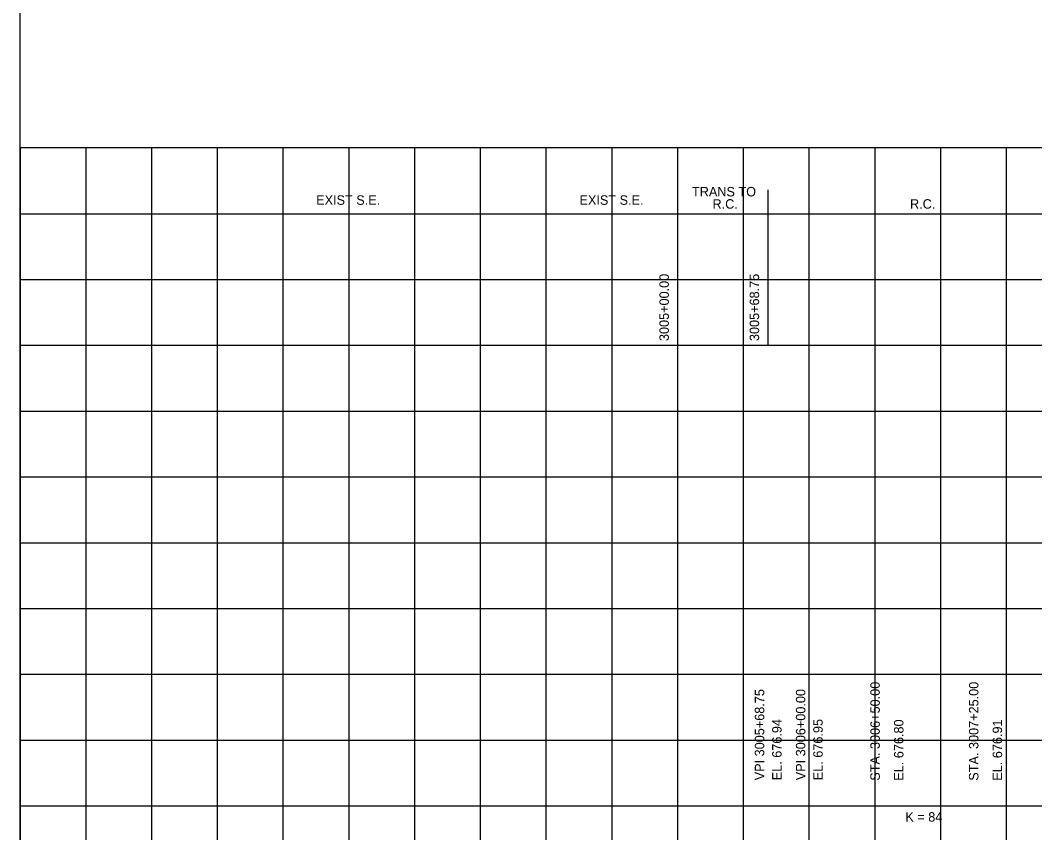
# Model space of a CAD drawing. Extents: x -7164 to 2214450, y -19642 to 253469.
# Drawn here: x 0 to 771, y 9480 to 10097 of the extents above; entities that cross this region are included whole.
import ezdxf

# ---------------------------------------------------------------- set-up
doc = ezdxf.new("R2010")
doc.units = 0
for name, color, linetype in [('DESIGN - PROFILE - Proposed Curve Text', 7, 'Continuous'), ('DESIGN - PROFILE - Proposed Text', 7, 'Continuous'), ('DESIGN - SCRATCH - User 1', 7, 'Continuous'), ('DESIGN - SHEET - Light Grid', 7, 'Continuous')]:
    doc.layers.add(name, color=color, linetype=linetype)

msp = doc.modelspace()

# ---------------------------------------------------------------- linework, layer by layer
at = {"layer": 'DESIGN - PROFILE - Proposed Curve Text'}
for p, q in [((500, 9850), (500, 9968.1)), ((500, 9850), (500, 9968.1)), ((568.75, 9850), (568.75, 9968.1)), ((568.75, 9850), (568.75, 9968.1)), ((0, 9950), (500, 9950)), ((0, 9950), (500, 9950)), ((500, 9950), (568.75, 9950)), ((500, 9950), (568.75, 9950)), ((568.75, 9950), (803.66, 9950)), ((568.75, 9950), (803.66, 9950))]:
    msp.add_line(p, q, dxfattribs=at)
at = {"layer": 'DESIGN - SCRATCH - User 1'}
for p, q in [((2600, 10000), (0, 10000)), ((0, 10000), (0, 9000)), ((2600, 10000), (0, 10000)), ((0, 10000), (0, 9000))]:
    msp.add_line(p, q, dxfattribs=at)
msp.add_lwpolyline([(500, 9000), (500, 10000)], dxfattribs=at)
msp.add_lwpolyline([(500, 9000), (500, 10000)], dxfattribs=at)
at = {"layer": 'DESIGN - SHEET - Light Grid'}
for p, q in [((0, 9000), (0, 11500)), ((0, 9000), (0, 11500)), ((50, 9000), (50, 10000)), ((50, 9000), (50, 10000)), ((100, 9000), (100, 10000)), ((100, 9000), (100, 10000)), ((150, 9000), (150, 10000)), ((150, 9000), (150, 10000)), ((200, 9000), (200, 10000)), ((200, 9000), (200, 10000)), ((250, 9000), (250, 10000)), ((250, 9000), (250, 10000)), ((300, 9000), (300, 10000)), ((300, 9000), (300, 10000)), ((350, 9000), (350, 10000)), ((350, 9000), (350, 10000)), ((400, 9000), (400, 10000)), ((400, 9000), (400, 10000)), ((450, 9000), (450, 10000)), ((450, 9000), (450, 10000)), ((500, 9000), (500, 10000)), ((500, 9000), (500, 10000)), ((550, 9000), (550, 10000)), ((550, 9000), (550, 10000)), ((600, 9000), (600, 10000)), ((600, 9000), (600, 10000)), ((650, 9000), (650, 10000)), ((650, 9000), (650, 10000)), ((700, 9000), (700, 10000)), ((700, 9000), (700, 10000)), ((750, 9000), (750, 10000)), ((750, 9000), (750, 10000)), ((0, 9950), (2600, 9950)), ((0, 9950), (2600, 9950)), ((0, 9900), (2600, 9900)), ((0, 9900), (2600, 9900)), ((0, 9850), (2600, 9850)), ((0, 9850), (2600, 9850)), ((0, 9800), (2600, 9800)), ((0, 9800), (2600, 9800)), ((0, 9750), (2600, 9750)), ((0, 9750), (2600, 9750)), ((0, 9700), (2600, 9700)), ((0, 9700), (2600, 9700)), ((0, 9650), (2600, 9650)), ((0, 9650), (2600, 9650)), ((0, 9600), (2600, 9600)), ((0, 9600), (2600, 9600)), ((0, 9550), (2600, 9550)), ((0, 9550), (2600, 9550)), ((0, 9500), (2600, 9500)), ((0, 9500), (2600, 9500))]:
    msp.add_line(p, q, dxfattribs=at)

# ---------------------------------------------------------------- texts
at = {"layer": 'DESIGN - PROFILE - Proposed Curve Text'}
for s, p in [('TRANS TO', (510.81, 9963.15)), ('EXIST S.E.', (225, 9956.8)), ('EXIST S.E.', (425.25, 9956.8)), ('R.C.', (526.39, 9953.83)), ('R.C.', (676.58, 9953.83)), ('K = 84', (673.07, 9488.02)), ('K = 84', (673.07, 9488.02))]:
    msp.add_text(s, height=7.2, dxfattribs=at).set_placement(p)
for s, rotation, p in [('TRANS TO', 360, (510.81, 9963.15)), ('EXIST S.E.', 360, (225, 9956.8)), ('EXIST S.E.', 360, (425.25, 9956.8)), ('R.C.', 360, (526.39, 9953.83)), ('R.C.', 360, (676.58, 9953.83)), ('3005+00.00', 90, (493.2, 9853.23)), ('3005+00.00', 90, (493.2, 9853.23)), ('3005+68.75', 90, (561.83, 9853.23)), ('3005+68.75', 90, (561.83, 9853.23)), ('VPI 3005+68.75', 90, (565.75, 9519.43)), ('VPI 3005+68.75', 90, (565.75, 9519.43)), ('VPI 3006+00.00', 90, (597, 9519.48)), ('VPI 3006+00.00', 90, (597, 9519.48)), ('EL. 676.94', 90, (578.95, 9519.43)), ('EL. 676.94', 90, (578.95, 9519.43)), ('EL. 676.95', 90, (610.2, 9519.48)), ('EL. 676.95', 90, (610.2, 9519.48))]:
    msp.add_text(s, height=7.2, rotation=rotation, dxfattribs=at).set_placement(p)
at = {"layer": 'DESIGN - PROFILE - Proposed Text'}
for s, p in [('STA. 3006+50.00 ', (653.6, 9519.12)), ('STA. 3006+50.00 ', (653.6, 9519.12)), ('STA. 3007+25.00 ', (728.6, 9519.12)), ('STA. 3007+25.00 ', (728.6, 9519.12)), ('EL. 676.80', (671.6, 9519.12)), ('EL. 676.80', (671.6, 9519.12)), ('EL. 676.91', (746.6, 9519.12)), ('EL. 676.91', (746.6, 9519.12))]:
    msp.add_text(s, height=7.2, rotation=90, dxfattribs=at).set_placement(p)

doc.saveas('drawing.dxf')
